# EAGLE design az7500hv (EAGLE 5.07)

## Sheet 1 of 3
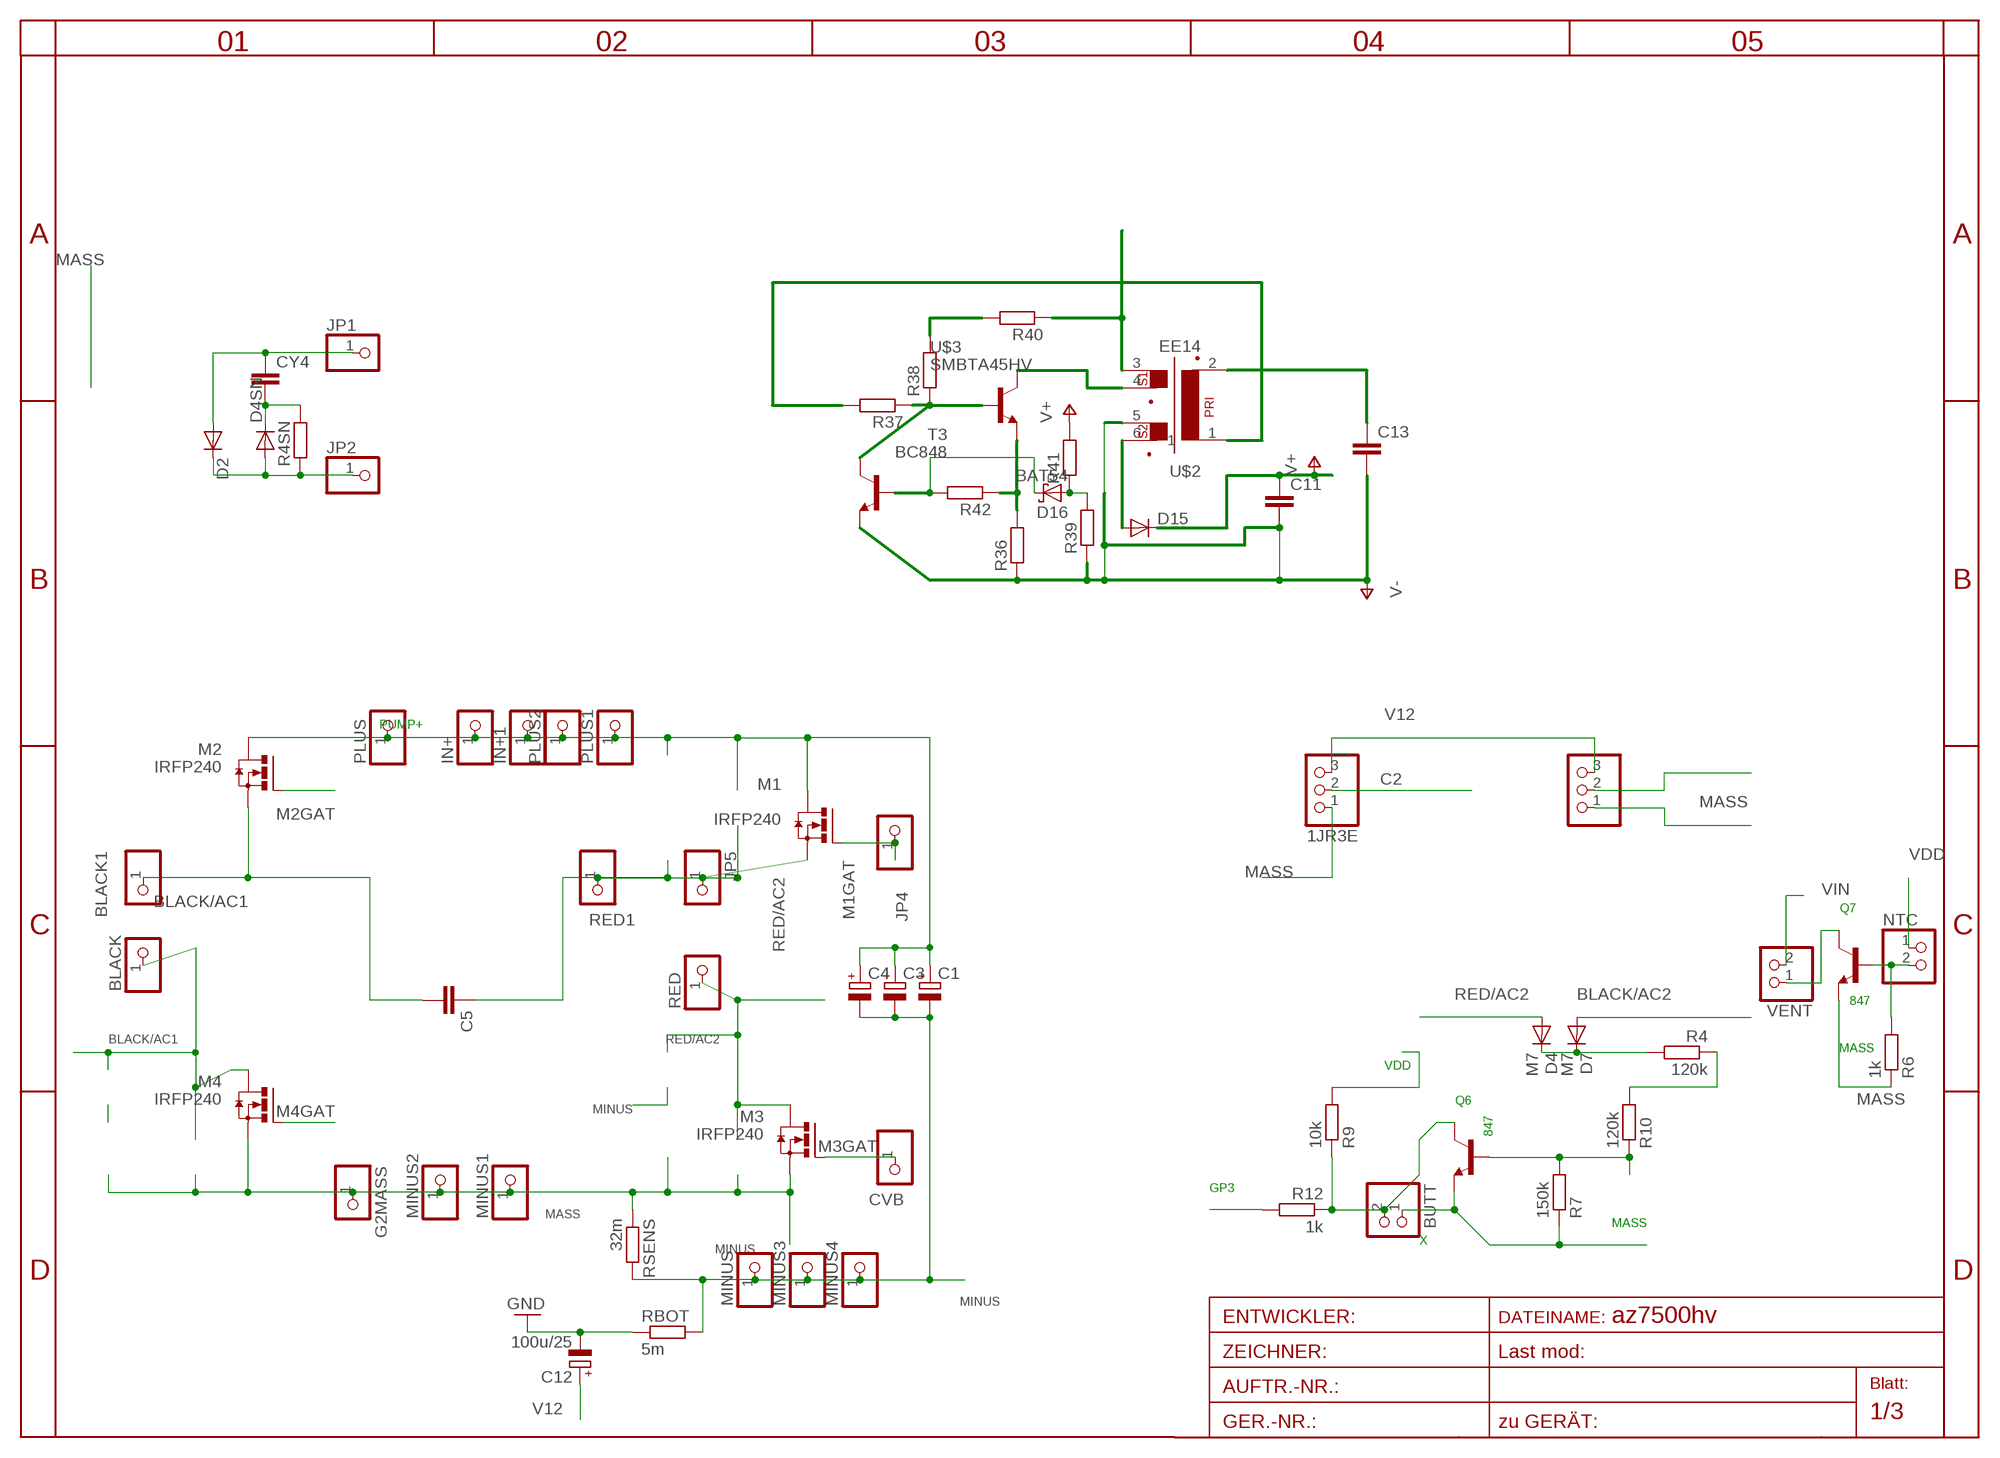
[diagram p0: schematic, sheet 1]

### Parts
1JR3E  PINHD-1X3  [1X03]
2JR4E3  PINHD-1X3  [1X03]
BLACK  PINHD-1X12MM3  [1X2MM3]
BLACK1  PINHD-1X12MM3  [1X2MM3]
BUTT  PINHD-1X2STR  [1X02]
C1  CPOL-EUE5-13  [E5-13]
C3  CPOL-EUE5-13  [E5-13]
C4  CPOL-EUE5-13  [E5-13]
C5  C-EU075-032X103  [C075-032X103]
C11  C-EUC1206  [C1206]
C12  100u/25  CPOL-EUE2.5-7  [E2,5-7]
C13  C-EUC0805  [C0805]
CVB  PINHD-1X11MM0  [1X1MM0]
CY4  CXXC10B5  [XC10B5]
D2  DIODE-SMC  [SMC]
D4  M7  1N4004DO41-10  [DO41-10]
D4SN  DIODE-P1-10  [P1-10]
D7  M7  1N4004DO41-10  [DO41-10]
D15  DIODE-SMA-DO214  [SMA-DO214AC]
D16  BAT54  [SOT23]
G2MASS  PINHD-1X11MM0  [1X1MM0]
IN+  PINHD-1X12MM3  [1X2MM3]
IN+1  PINHD-1X12MM3  [1X2MM3]
JP1  PINHD-1X11MM0  [1X1MM0]
JP2  PINHD-1X11MM0  [1X1MM0]
JP4  PINHD-1X11MM0  [1X1MM0]
JP5  PINHD-1X11MM0  [1X1MM0]
M1  IRFP240  [TO247BV]
M2  IRFP240  [TO247BV]
M3  IRFP240  [TO247BV]
M4  IRFP240  [TO247BV]
MINUS  PINHD-1X12MM3  [1X2MM3]
MINUS1  PINHD-1X12MM3  [1X2MM3]
MINUS2  PINHD-1X12MM3  [1X2MM3]
MINUS3  PINHD-1X12MM3  [1X2MM3]
MINUS4  PINHD-1X12MM3  [1X2MM3]
NTC  PINHD-1X2STR  [1X02]
PLUS  PINHD-1X12MM3  [1X2MM3]
PLUS1  PINHD-1X12MM3  [1X2MM3]
PLUS2  PINHD-1X12MM3  [1X2MM3]
Q6  847  BC847ALT1SMD  [SOT23]
Q7  847  BC847ALT1SMD  [SOT23]
R4  120k  R-EU_R1210  [R1210]
R4SN  R-EU_0207/10  [0207/10]
R6  1k  R-EU_R0805  [R0805]
R7  150k  R-EU_R0805  [R0805]
R9  10k  R-EU_R0805  [R0805]
R10  120k  R-EU_R1210  [R1210]
R12  1k  R-EU_R0805  [R0805]
R36  R-EU_R0805  [R0805]
R37  R-EU_R0805  [R0805]
R38  R-EU_R1206  [R1206]
R39  R-EU_R0805  [R0805]
R40  R-EU_R1206  [R1206]
R41  R-EU_R0805  [R0805]
R42  R-EU_R0805  [R0805]
RBOT  5m  R-EU_0204/7  [0204/7]
RED  PINHD-1X12MM3  [1X2MM3]
RED1  PINHD-1X12MM3  [1X2MM3]
RSENS  32m  R-EU_0204/7  [0204/7]
T3  BC848  [SOT23]
U$2  EE14  EE14EE14  [EE14]
U$3  SMBTA45HV  [SOT23HV]
VENT  PINHD-1X2STR  [1X02]

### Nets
A: D15.A U$2.6
B1C2: R37.1 R38.1 T3.C U$3.1(B)
BLACK/AC1: BLACK1.1 BLACK.1 C5.2 M2.S M4.D ; also sheet 2
BLACK/AC2: D7.A ; also sheet 2
C1: 2JR4E3.2 ; also sheet 2,3
C2: 1JR3E.2 ; also sheet 2,3
C3: U$2.4 U$3.3(C)
DRAIN: D2.C D4SN.A JP2.1 R4SN.1
EB: R36.2 R42.1 U$3.2(E)
GND: C12.- RBOT.1 ; also sheet 2
GP3: R12.2 ; also sheet 3
M1GAT: JP4.1 M1.G ; also sheet 2
M2GAT: M2.G ; also sheet 2
M3GAT: CVB.1 M3.G ; also sheet 2
M4GAT: M4.G ; also sheet 2
MASS: 1JR3E.1 2JR4E3.1 BUTT.1 G2MASS.1 M3.S M4.S MINUS1.1 MINUS2.1 Q6.2(E) Q7.2(E) R6.1 R7.1 RSENS.1 ; also sheet 2,3
MINUS: C1.- C3.- C4.- MINUS3.1 MINUS4.1 MINUS.1 RBOT.2 RSENS.2
N$1: D4.C D7.C R4.2
N$2: R37.2 U$2.1
N$5: Q6.1(B) R7.2 R10.1
N$7: R4.1 R10.2
N$9: NTC.2 Q7.1(B) R6.2
N$10: Q7.3(C) VENT.1
N$16: C13.1 U$2.2
N$37: R38.2 R40.2
N$38: D16.1(A) R39.2 R41.1
N$39: D16.3(C) R42.2 T3.B
OUT+: R40.1 U$2.3
PUMP+: C1.+ C3.+ C4.+ IN+1.1 IN+.1 M1.D M2.D PLUS1.1 PLUS2.1 PLUS.1 ; also sheet 3
RED/AC2: C5.1 D4.A JP5.1 M1.S M3.D RED1.1 RED.1 ; also sheet 2
SNUB2: CY4.2 D4SN.C R4SN.2
SOURCE: CY4.1 D2.A JP1.1
V12: 1JR3E.3 2JR4E3.3 C12.+
V+: C11.1 D15.K(C) R41.2
V-: C11.2 C13.2 R36.1 R39.1 T3.E U$2.5
VDD: NTC.1 R9.2 ; also sheet 3
VIN: VENT.2
X: BUTT.2 Q6.3(C) R9.1 R12.1

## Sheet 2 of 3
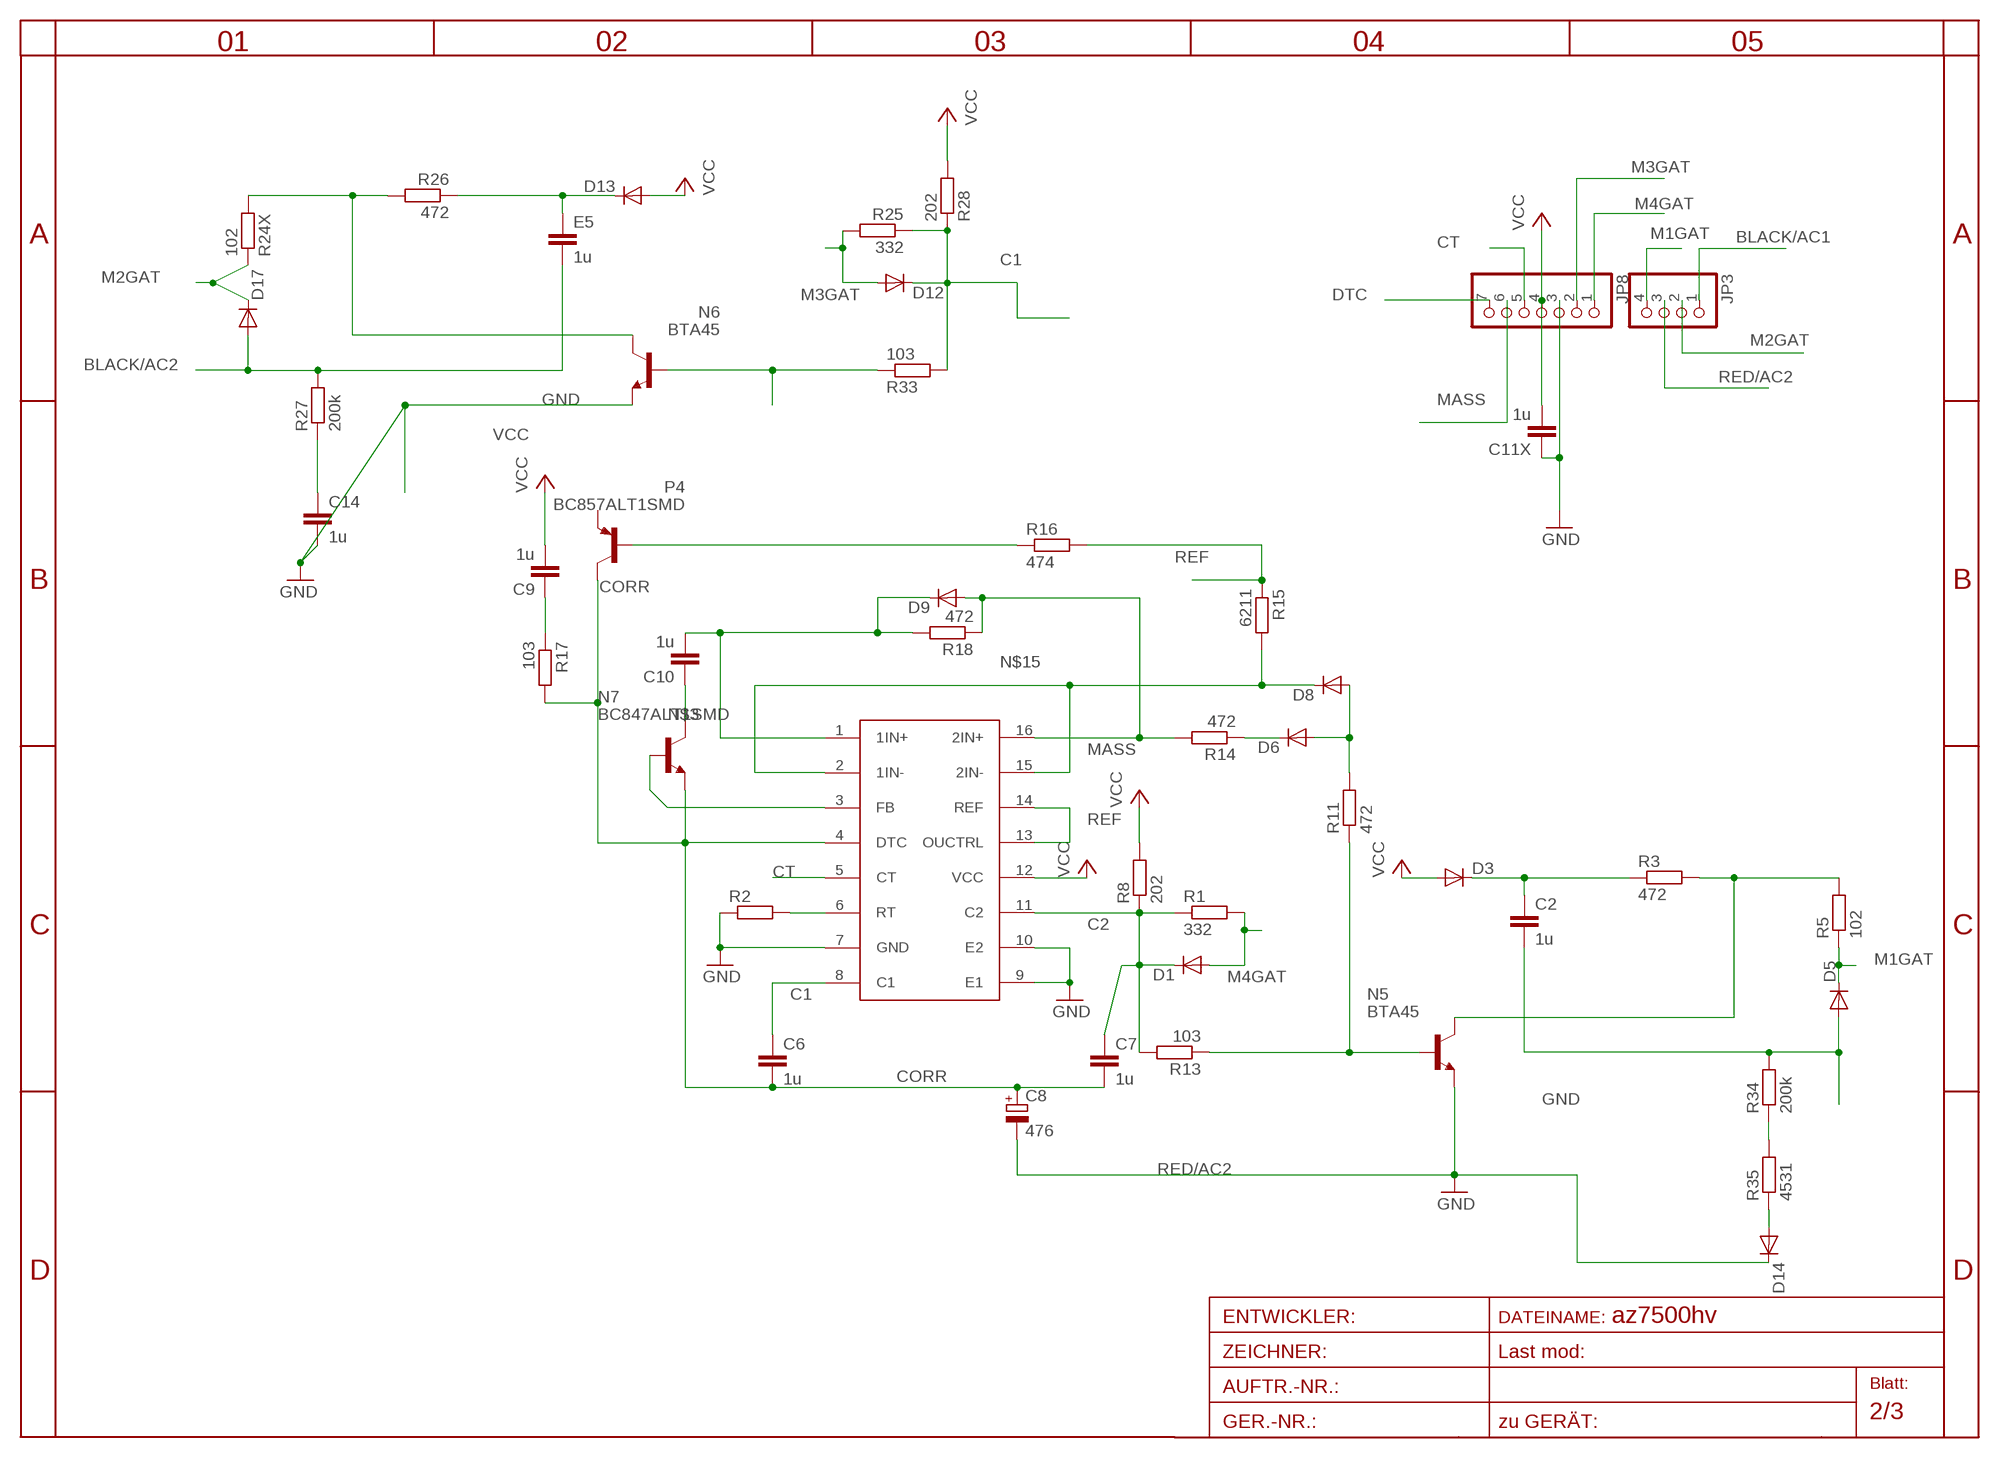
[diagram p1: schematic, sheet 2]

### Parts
C2  1u  C-EUC1206  [C1206]
C6  1u  C-EUC0805  [C0805]
C7  1u  C-EUC0805  [C0805]
C8  476  CPOL-EUD  [PANASONIC_D]
C9  1u  C-EUC0805  [C0805]
C10  1u  C-EUC0805  [C0805]
C11X  1u  C-EUC1206  [C1206]
C14  1u  C-EUC1206  [C1206]
D1  DIODE-MINIMELF  [MINIMELF]
D3  DIODE-SMA-DO214  [SMA-DO214AC]
D5  DIODE-MINIMELF  [MINIMELF]
D6  DIODE-MINIMELF  [MINIMELF]
D8  DIODE-MINIMELF  [MINIMELF]
D9  DIODE-MINIMELF  [MINIMELF]
D12  DIODE-MINIMELF  [MINIMELF]
D13  DIODE-SMA-DO214  [SMA-DO214AC]
D14  DIODE-MINIMELF  [MINIMELF]
D17  DIODE-MINIMELF  [MINIMELF]
E5  1u  C-EUC1206  [C1206]
JP3  PINHD-1X4  [1X04]
JP8  PINHD-1X7  [1X07]
N5  BTA45  SMBTA45HV  [SOT23HV]
N6  BTA45  SMBTA45HV  [SOT23HV]
N7  BC847ALT1SMD  [SOT23]
P4  BC857ALT1SMD  [SOT23-BEC]
R1  332  R-EU_R0805  [R0805]
R2  R-EU_R0805  [R0805]
R3  472  R-EU_R0805  [R0805]
R5  102  R-EU_R1206  [R1206]
R8  202  R-EU_R0805  [R0805]
R11  472  R-EU_R0805  [R0805]
R13  103  R-EU_0207/15  [0207/15]
R14  472  R-EU_R0805  [R0805]
R15  6211  R-EU_R1206  [R1206]
R16  474  R-EU_R1206  [R1206]
R17  103  R-EU_R1206  [R1206]
R18  472  R-EU_R0805  [R0805]
R24X  102  R-EU_R1206  [R1206]
R25  332  R-EU_R0805  [R0805]
R26  472  R-EU_R0805  [R0805]
R27  200k  R-EU_R0805  [R0805]
R28  202  R-EU_R0805  [R0805]
R33  103  R-EU_0207/15  [0207/15]
R34  200k  R-EU_R0805  [R0805]
R35  4531  R-EU_R0805  [R0805]
U$1  AZ7500SO16  [SO16]

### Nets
BLACK/AC1: JP3.1 ; also sheet 1
BLACK/AC2: D17.A E5.2 R27.2 ; also sheet 1
C1: C6.1 D12.C R25.1 R28.1 R33.2 U$1.8(C1) ; also sheet 1,3
C2: C7.1 D1.C R1.1 R8.1 R13.2 U$1.11(C2) ; also sheet 1,3
CORR: C6.2 C7.2 C8.+ N7.2(E) P4.C R17.2 U$1.4(DTC)
CT: JP8.5 U$1.5(CT)
DTC: JP8.7
GND: C8.- C11X.1 C14.2 D14.C JP8.3 N5.2(E) N6.2(E) R2.1 U$1.7(GND) U$1.9(E1) U$1.10(E2) ; also sheet 1
M1GAT: D5.C JP3.4 R5.1 ; also sheet 1
M2GAT: D17.C JP3.2 R24X.1 ; also sheet 1
M3GAT: D12.A JP8.2 R25.2 ; also sheet 1
M4GAT: D1.A JP8.1 R1.2 ; also sheet 1
MASS: D9.A JP8.6 R14.2 R18.1 U$1.16(2IN+) ; also sheet 1,3
N$3: C10.2 D9.C R18.2 U$1.1(1IN+)
N$4: C2.1 D3.K(C) R3.1
N$6: D6.A D8.A R11.2
N$8: N5.3(C) R3.2 R5.2
N$11: D6.C R14.1
N$13: D13.K(C) E5.1 R26.1
N$14: C14.1 R27.1
N$15: D8.C R15.2 U$1.2(1IN-) U$1.15(2IN-)
N$17: N5.1(B) R11.1 R13.1
N$18: C9.1 R17.1
N$19: N6.3(C) R24X.2 R26.2
N$20: N7.1(B) U$1.3(FB)
N$21: P4.B R16.1
N$23: R2.2 U$1.6(RT)
N$25: C10.1 N7.3(C)
N$29: N6.1(B) R33.1
N$33: R34.1 R35.2
N$36: D14.A R35.1
RED/AC2: C2.2 D5.A JP3.3 R34.2 ; also sheet 1
REF: R15.1 R16.2 U$1.13(OUCTRL) U$1.14(REF)
VCC: C9.2 C11X.2 D3.A D13.A JP8.4 R8.2 R28.2 U$1.12(VCC)
Unconnected: P4.E

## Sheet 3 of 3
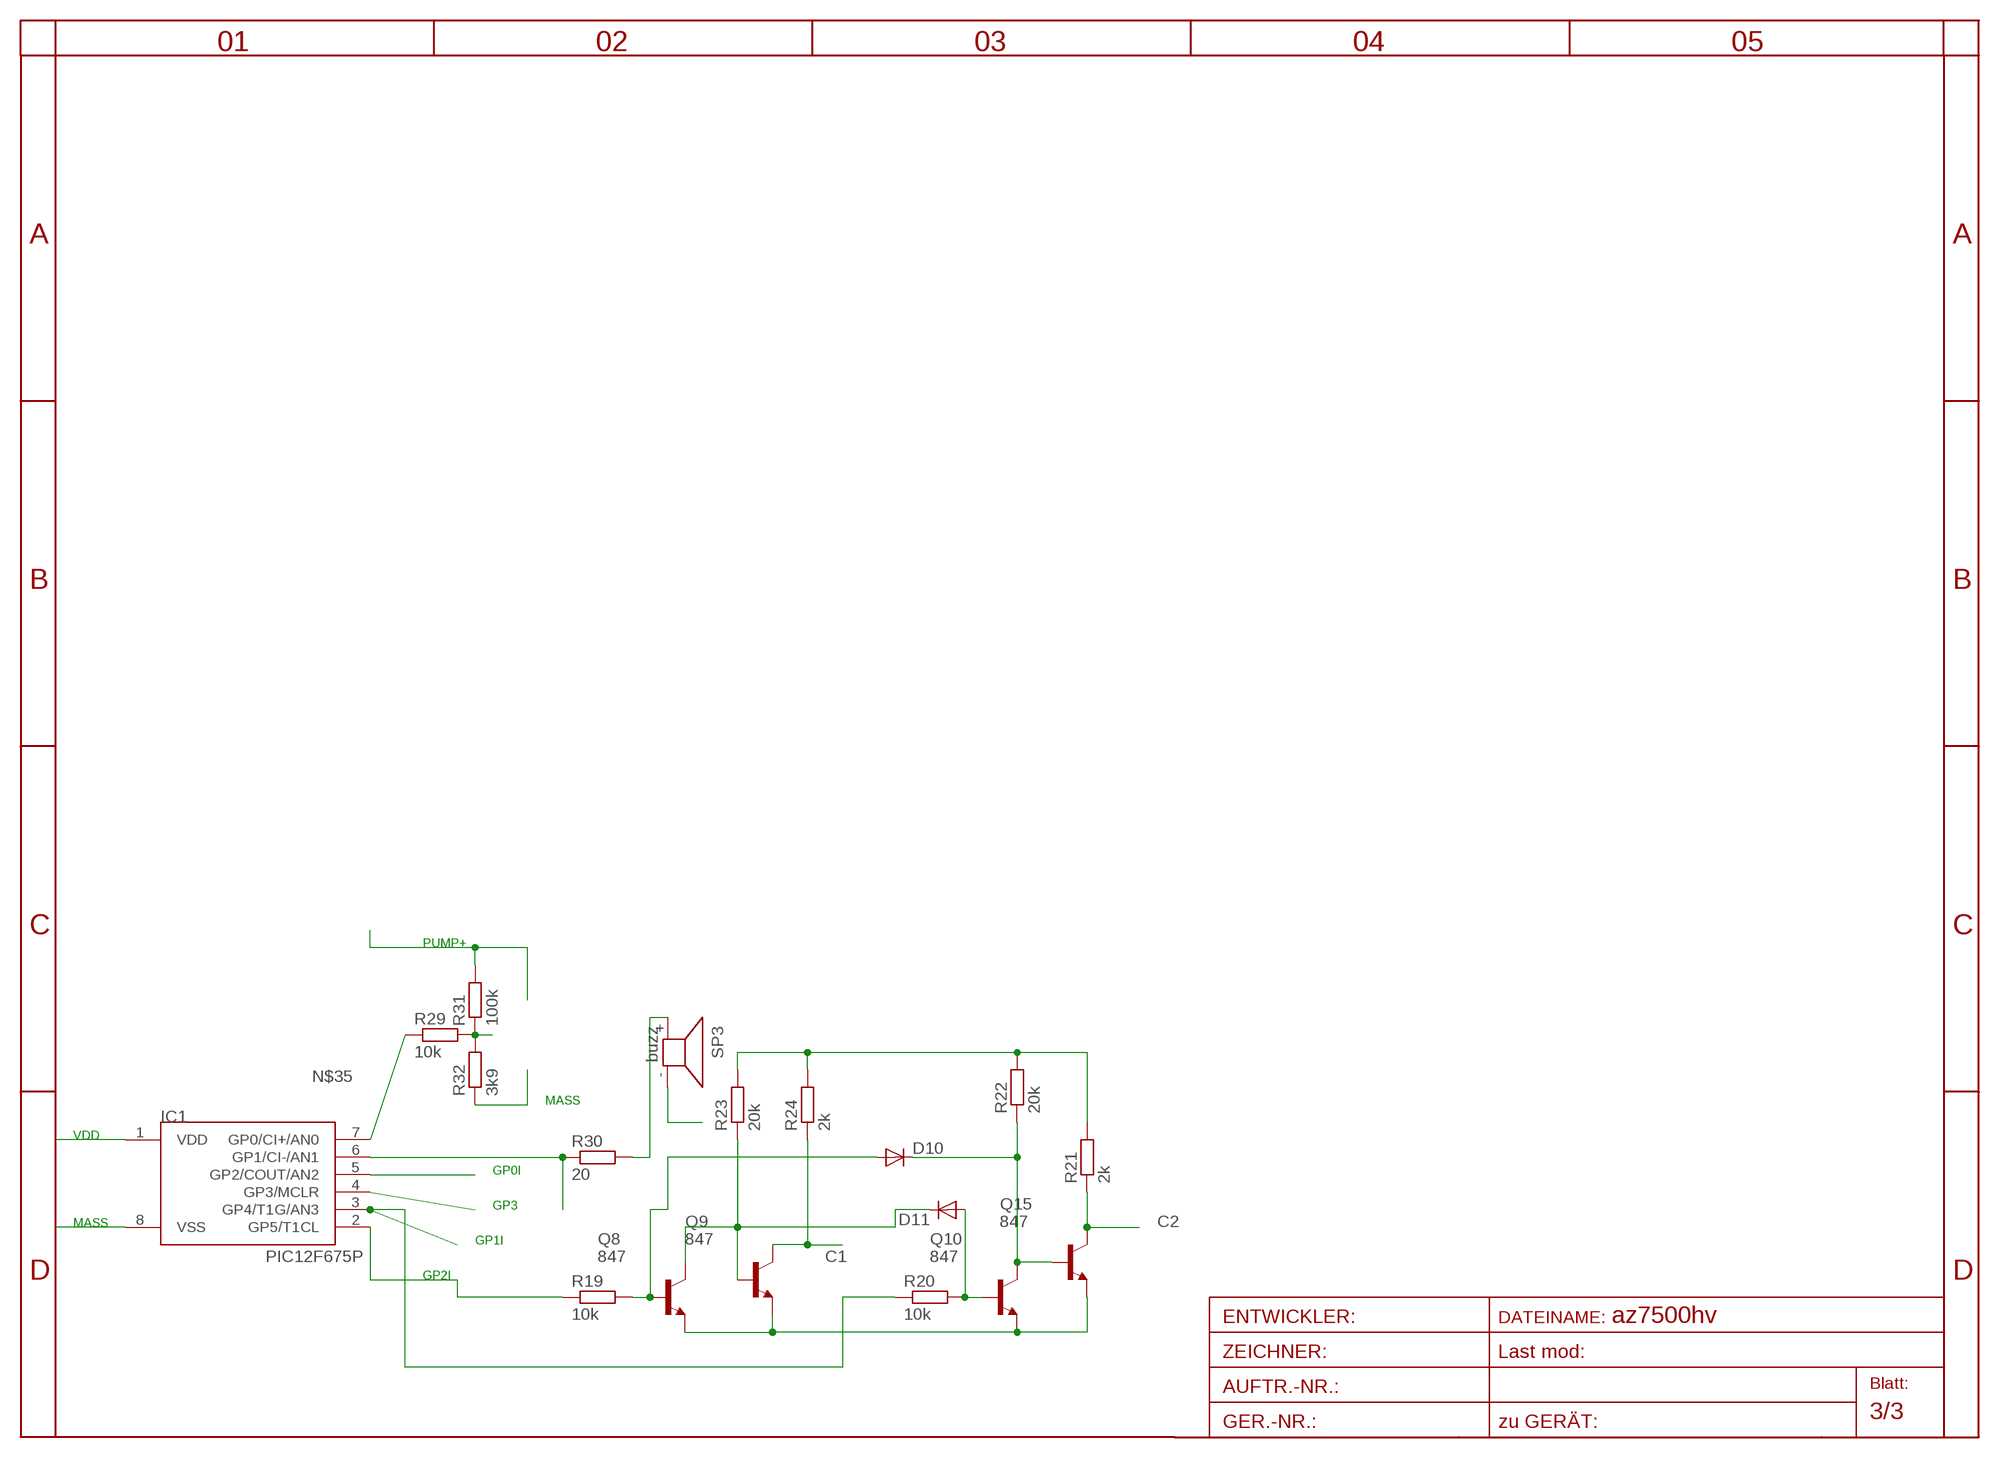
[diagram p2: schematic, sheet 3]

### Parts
D10  DIODE-MINIMELF  [MINIMELF]
D11  DIODE-MINIMELF  [MINIMELF]
IC1  PIC12F675P  [DIL8]
Q8  847  BC847ALT1SMD  [SOT23]
Q9  847  BC847ALT1SMD  [SOT23]
Q10  847  BC847ALT1SMD  [SOT23]
Q15  847  BC847ALT1SMD  [SOT23]
R19  10k  R-EU_R0805  [R0805]
R20  10k  R-EU_R0805  [R0805]
R21  2k  R-EU_R0805  [R0805]
R22  20k  R-EU_R0805  [R0805]
R23  20k  R-EU_R0805  [R0805]
R24  2k  R-EU_R0805  [R0805]
R29  10k  R-EU_R0805  [R0805]
R30  20  R-EU_R0805  [R0805]
R31  100k  R-EU_0207/25  [0207/25]
R32  3k9  R-EU_R0805  [R0805]
SP3  buzz  KSS12017MM  [KSS1202]

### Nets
C1: Q9.3(C) R24.1 ; also sheet 1,2
C2: Q15.3(C) R21.1 ; also sheet 1,2
GP0I: IC1.5(GP2/COUT/AN2)
GP1I: IC1.3(GP4/T1G/AN3) R20.1
GP2I: IC1.2(GP5/T1CL) R19.1
GP3: IC1.4(GP3/MCLR) ; also sheet 1
MASS: IC1.8(VSS) R32.1 SP3.- ; also sheet 1,2
N$22: D11.A Q10.1(B) R20.2
N$24: R30.2 SP3.+
N$26: D11.C Q8.3(C) Q9.1(B) R23.1
N$27: D10.C Q10.3(C) Q15.1(B) R22.1
N$28: D10.A Q8.1(B) R19.2
N$30: Q8.2(E) Q9.2(E) Q10.2(E) Q15.2(E)
N$31: IC1.6(GP1/CI-/AN1) R30.1
N$32: R21.2 R22.2 R23.2 R24.2
N$34: R29.2 R31.1 R32.2
N$35: IC1.7(GP0/CI+/AN0) R29.1
PUMP+: R31.2 ; also sheet 1
VDD: IC1.1(VDD) ; also sheet 1

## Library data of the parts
1JR3E 2JR4E3 = pinhead:PINHD-1X3: PIN HEADER
BLACK BLACK1 CVB G2MASS IN+ IN+1 JP1 JP2 JP4 JP5 MINUS MINUS1-MINUS4 PLUS PLUS1 PLUS2 RED RED1 = pinhead:PINHD-1X1: PIN HEADER
BUTT NTC VENT = pinhead:PINHD-1X2: PIN HEADER
C1 C3 C4 C8 C12 = rcl:CPOL-EU: POLARIZED CAPACITOR, European symbol
C2 C5-C7 C9-C11 C11X C13 C14 E5 = rcl:C-EU: CAPACITOR, European symbol
CY4 = rcl:CX: X CAPACITOR
D1-D3 D4SN D5 D6 D8-D15 D17 = diode:DIODE-: DIODE
D4 D7 = diode:1N4004: DIODE
D16 = diode:BAT54: Schottky Diodes
IC1 = microchip-5:PIC12F6*: uPC nW 1k Program Flash memory 2x Timer Comparator 10b A/D converter/ 4xIN
JP3 = pinhead:PINHD-1X4: PIN HEADER
JP8 = pinhead:PINHD-1X7: PIN HEADER
M1-M4 = transistor-power:IRFP240: HEXFET Power MosFet Source: http://www.irf.com/
N5 N6 U$3 = transistor-npn:SMBTA45
N7 Q6-Q10 Q15 = transistor-npn:BC847*: NPN Transistor
P4 = transistor-pnp:BC857*: PNP Transistror
R1-R4 R4SN R5-R18 R24X R25-R28 R33-R42 RBOT RSENS = rcl:R-EU_: RESISTOR, European symbol
R19-R24 R29-R32 = rcl-2:R-EU_: RESISTOR, European symbol
SP3 = buzzer:KSS1201: SPEAKER
T3 = transistor:BC848: NPN TRANSISTOR
U$1 = az7500:AZ7500
U$2 = trafo:EE14

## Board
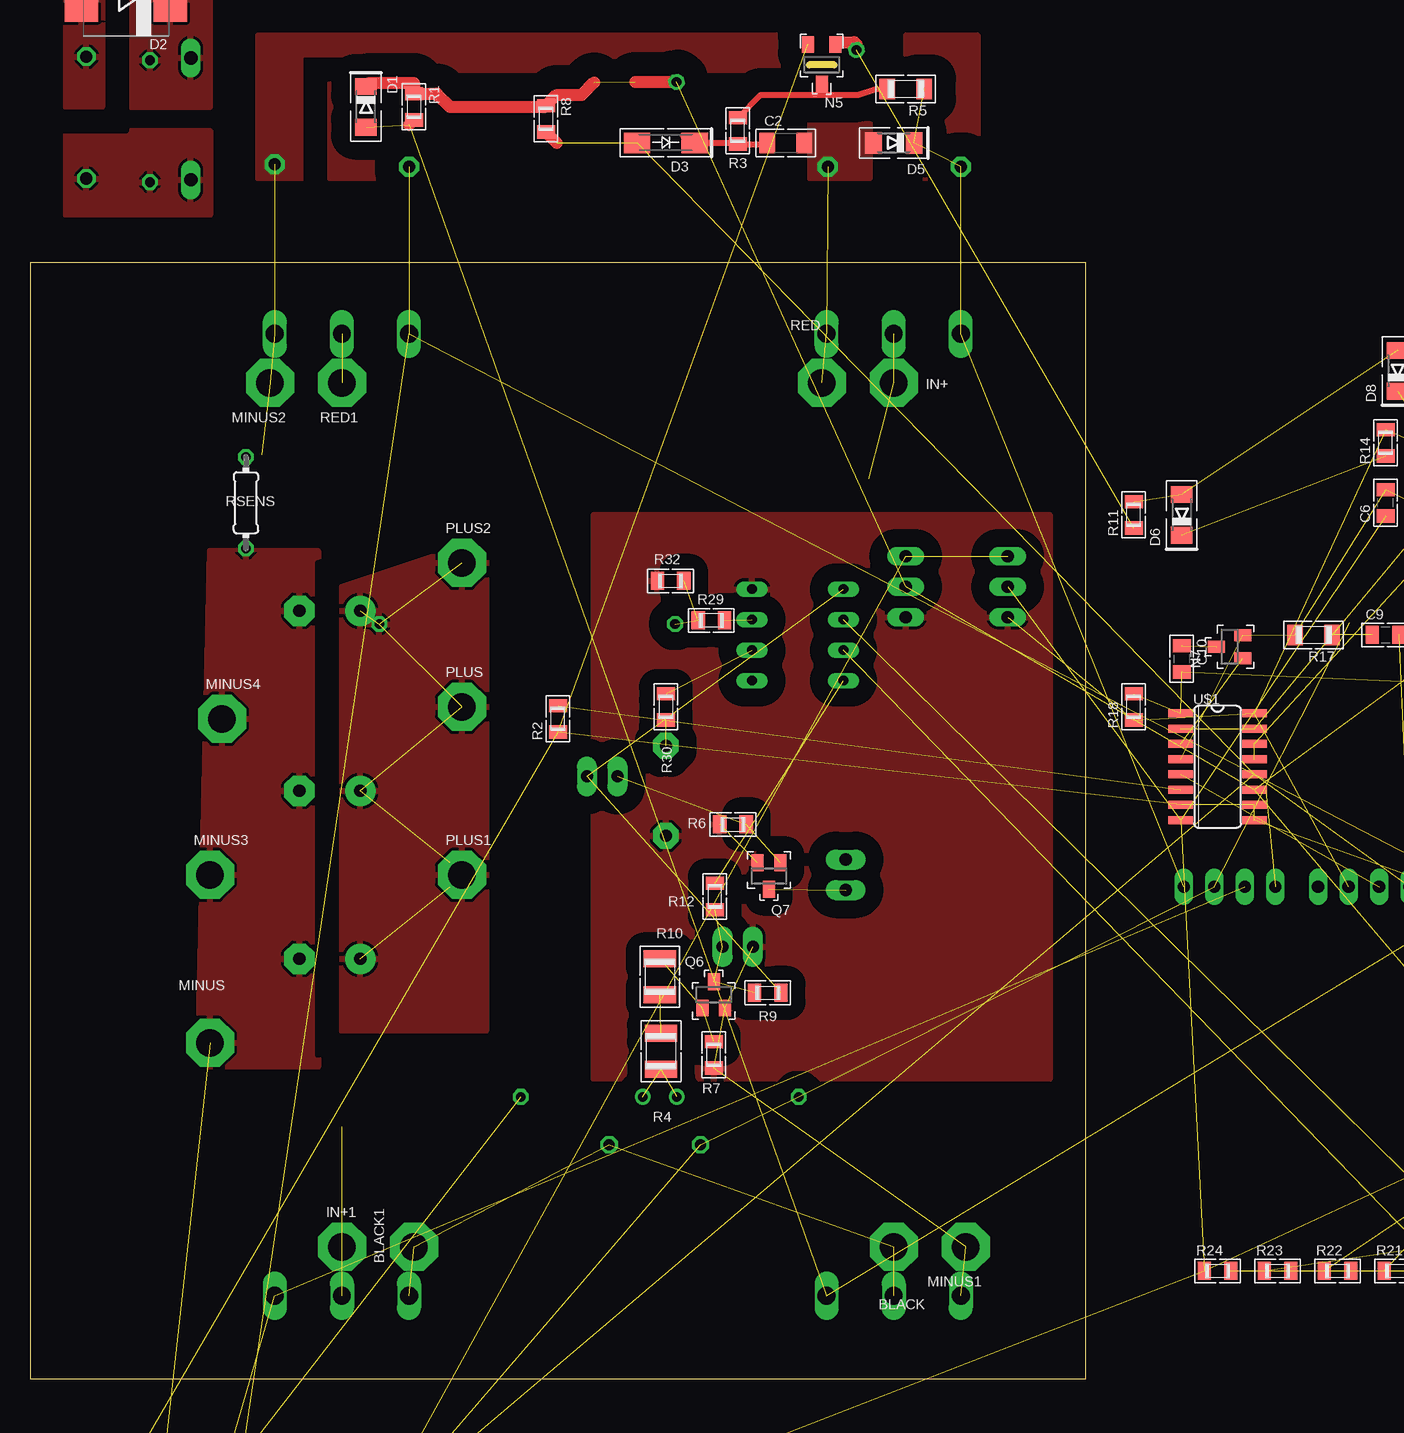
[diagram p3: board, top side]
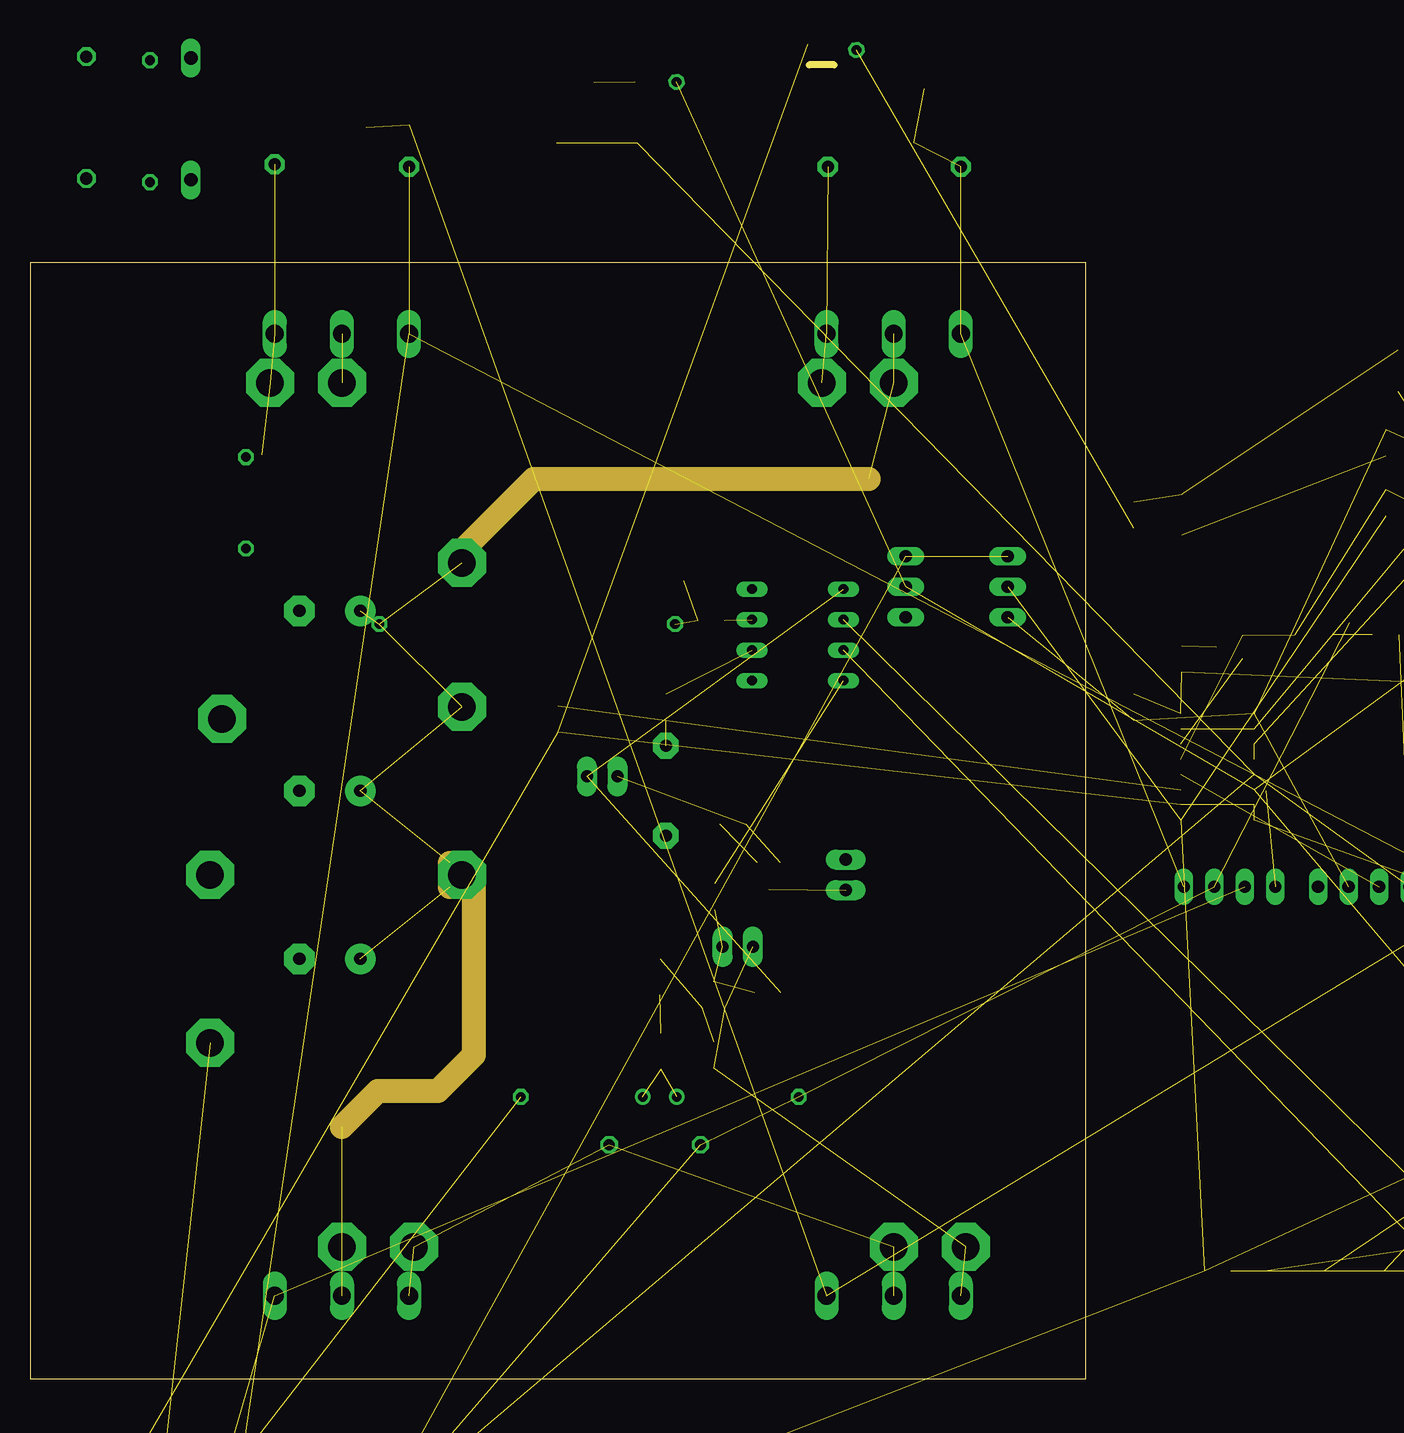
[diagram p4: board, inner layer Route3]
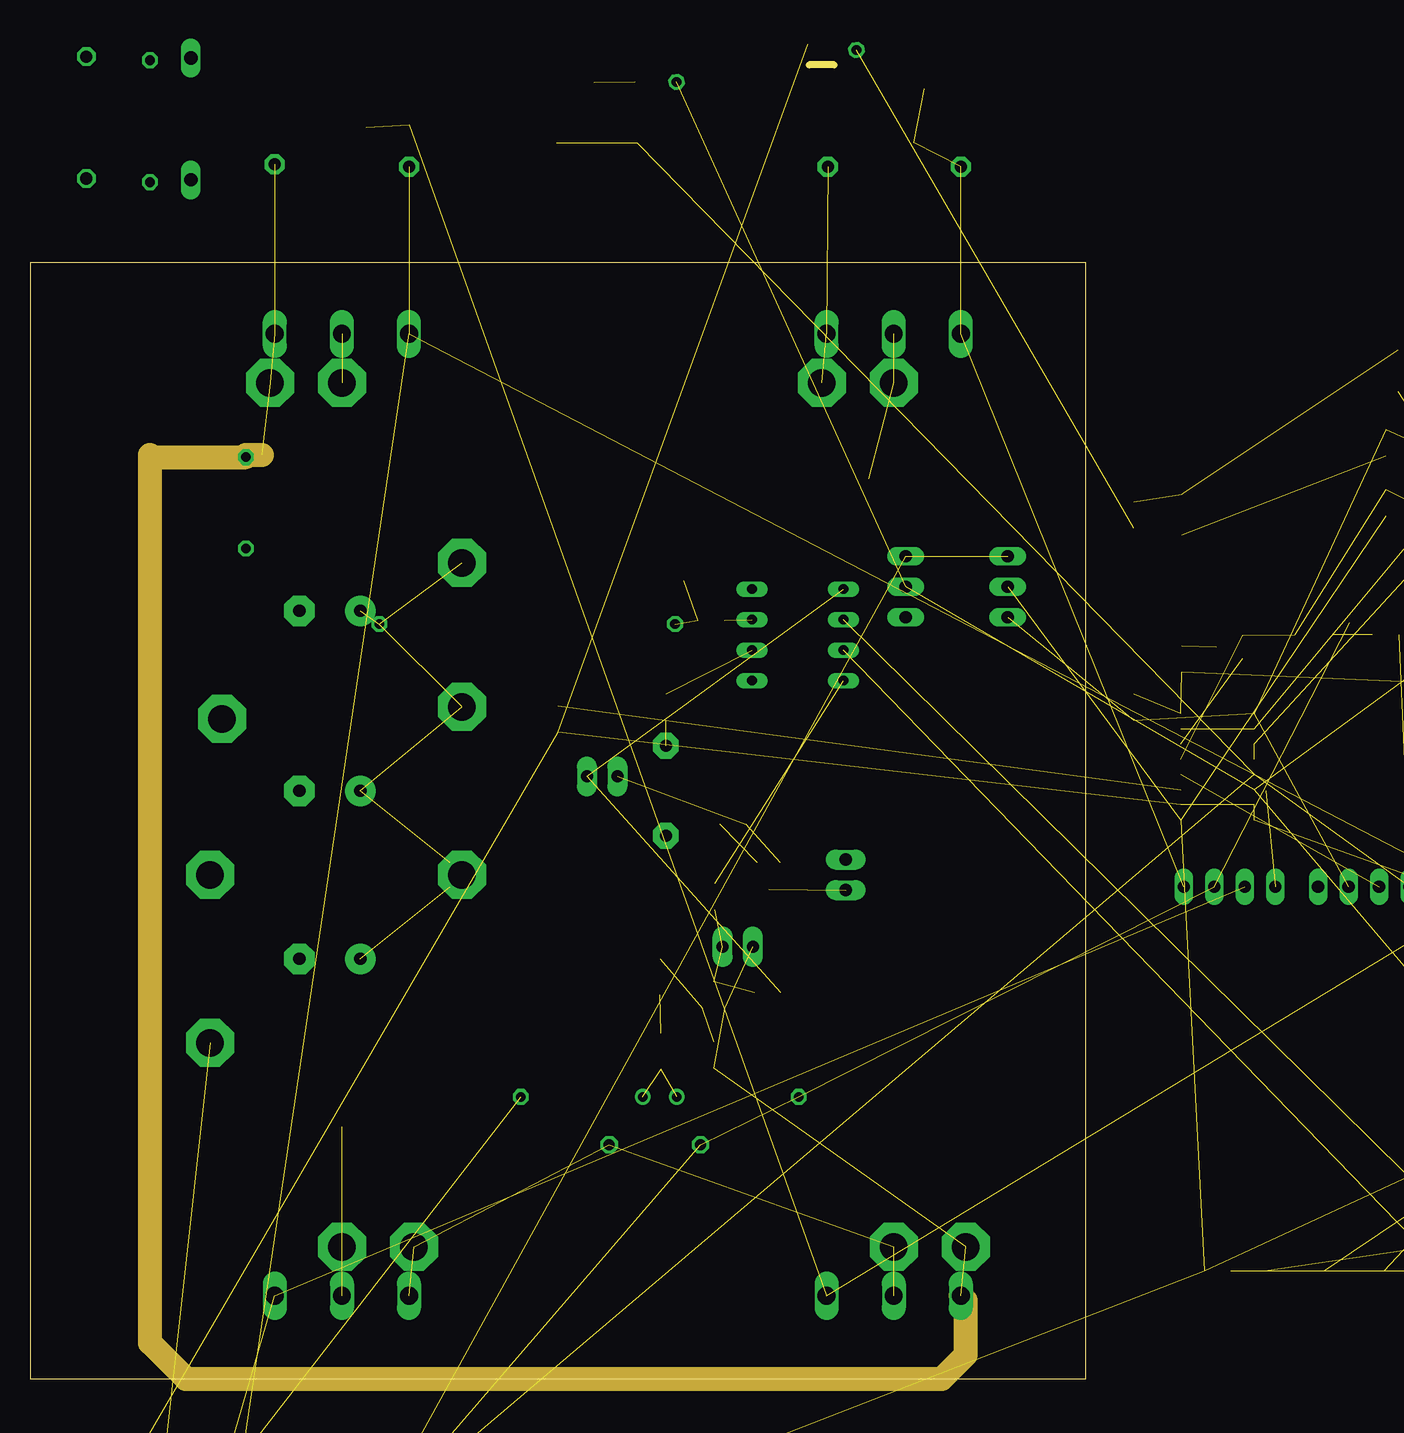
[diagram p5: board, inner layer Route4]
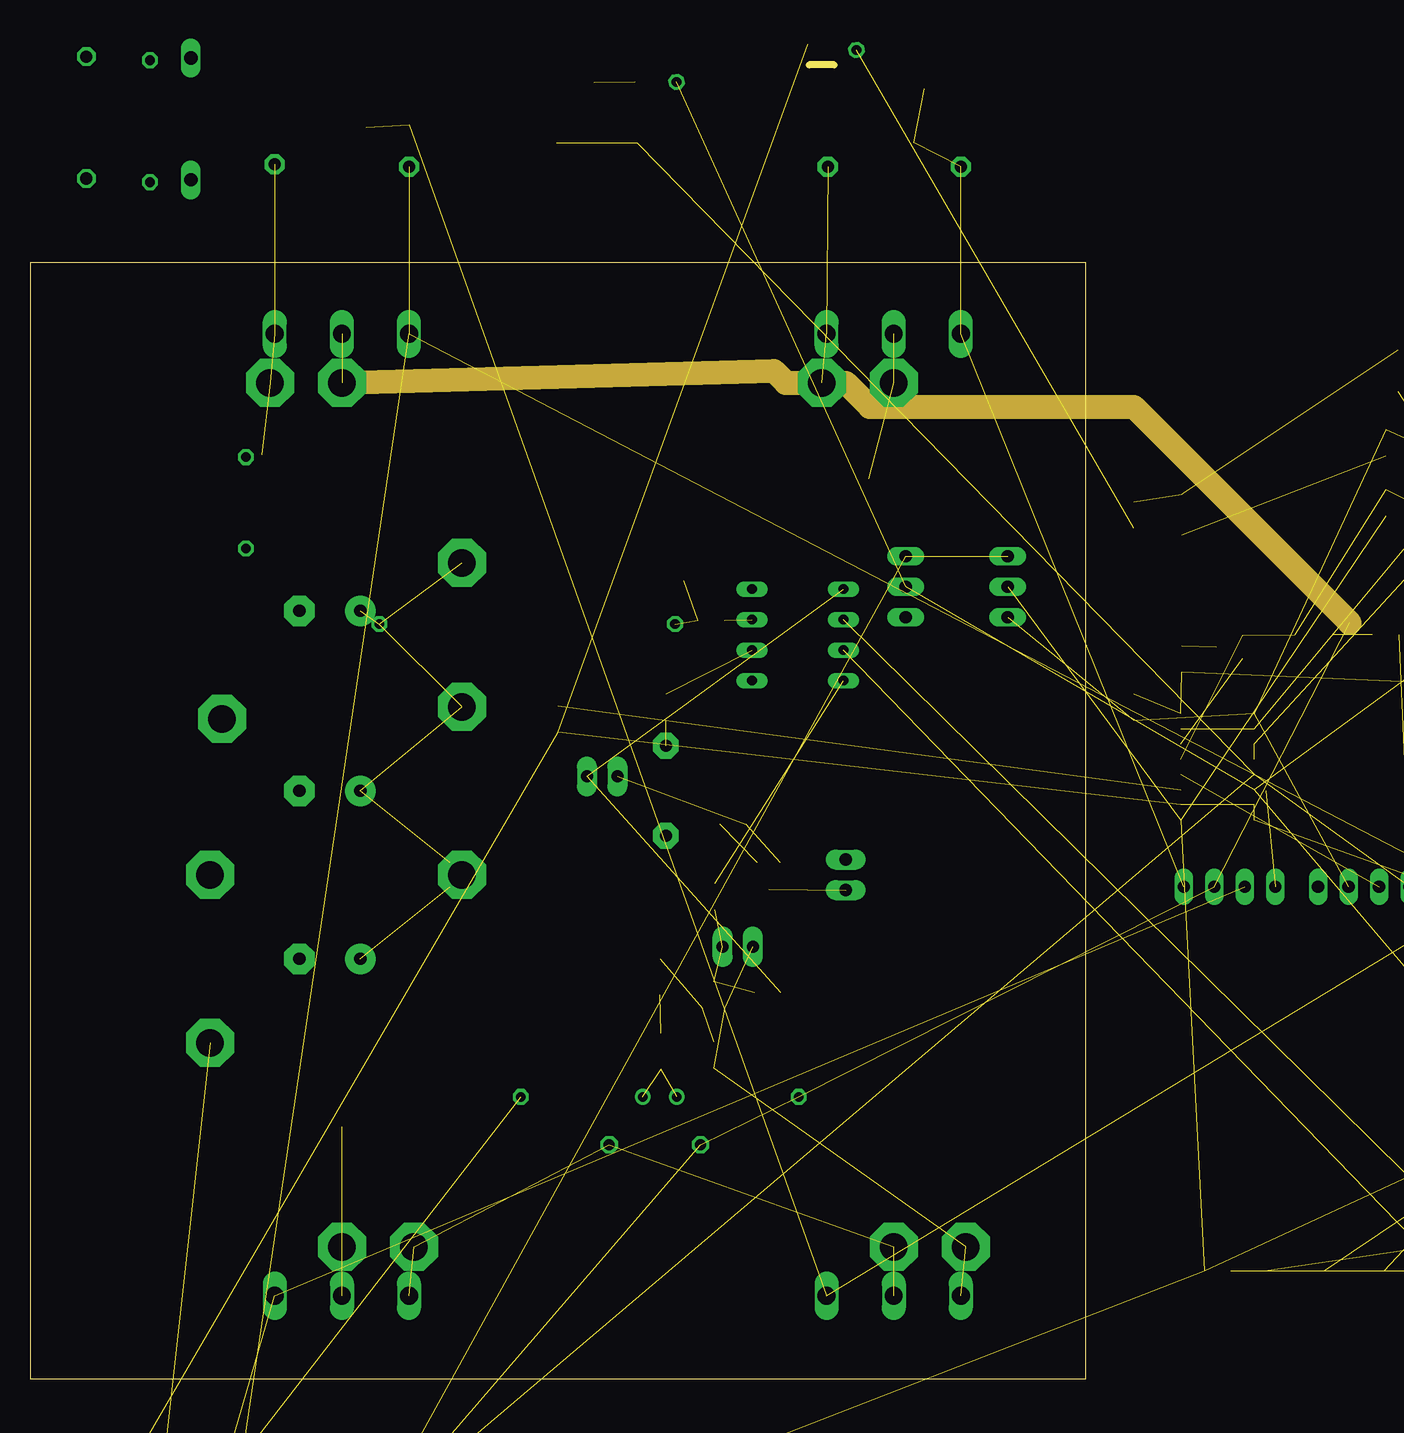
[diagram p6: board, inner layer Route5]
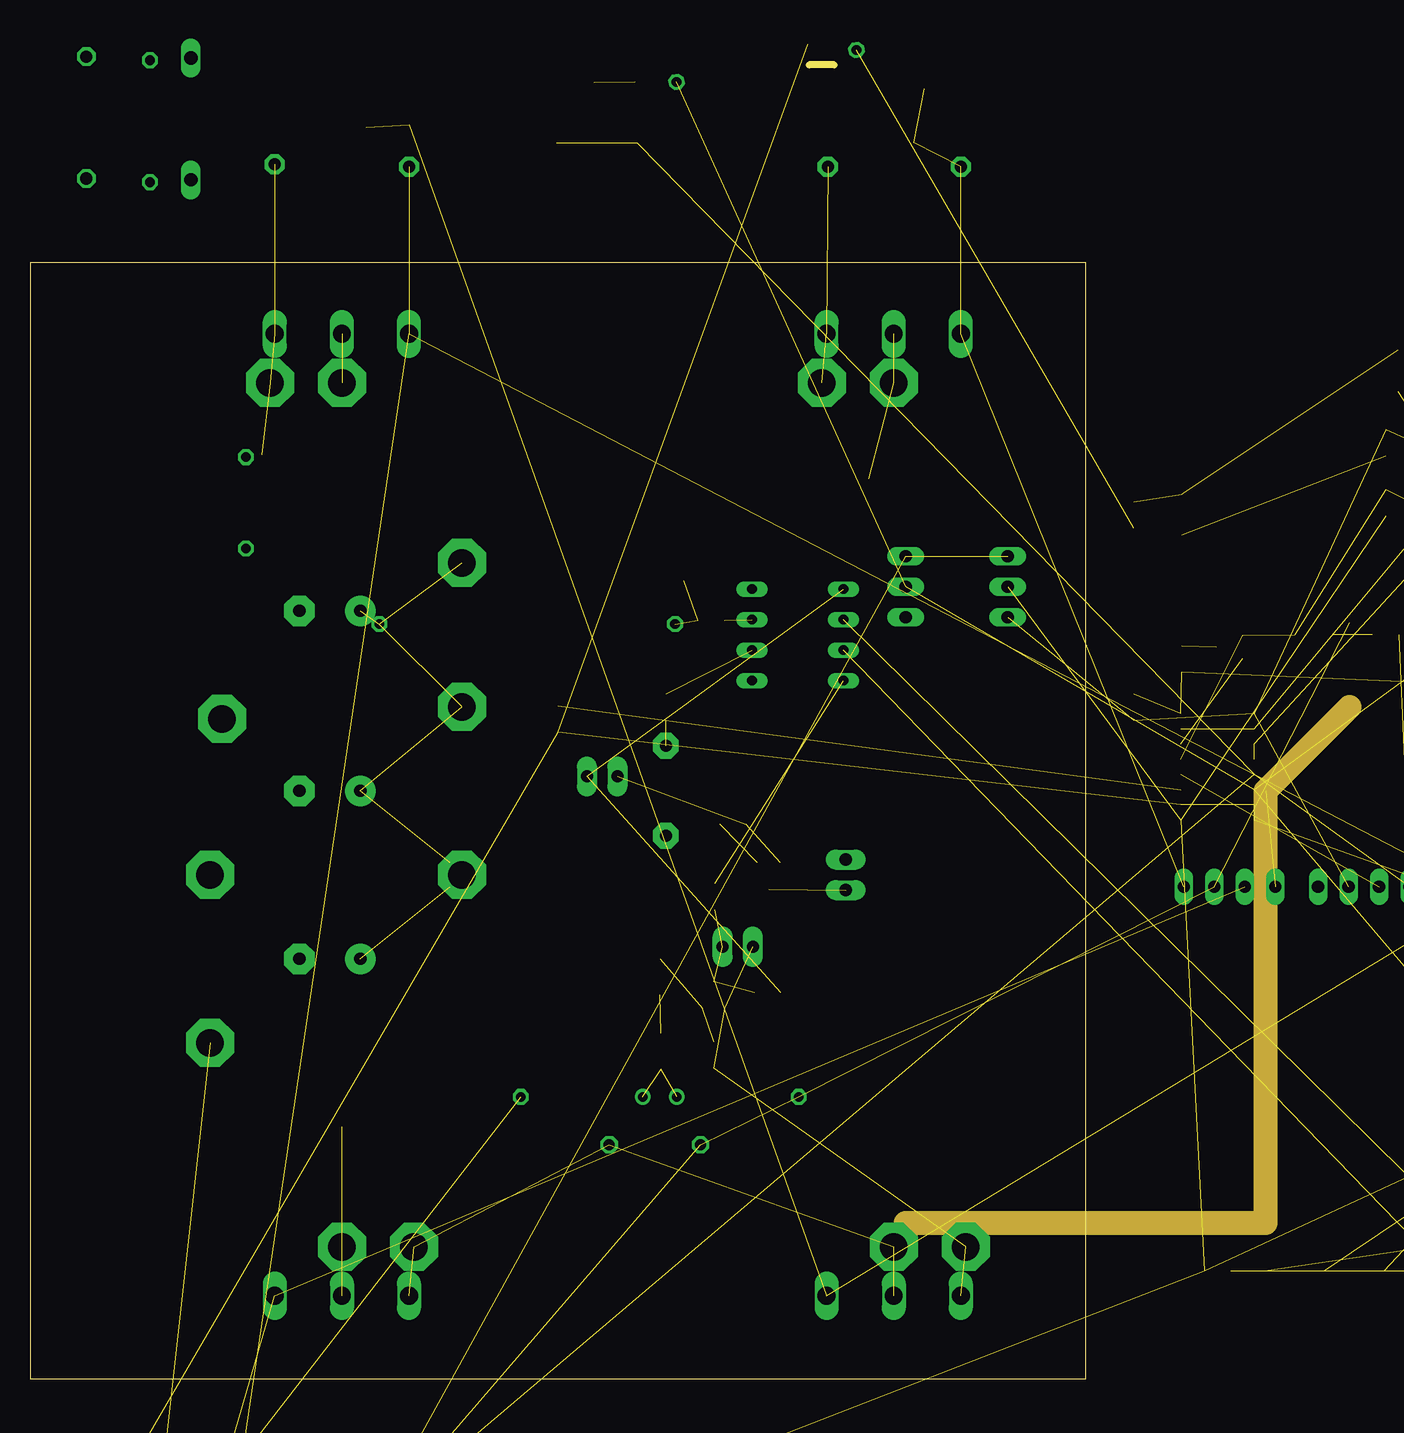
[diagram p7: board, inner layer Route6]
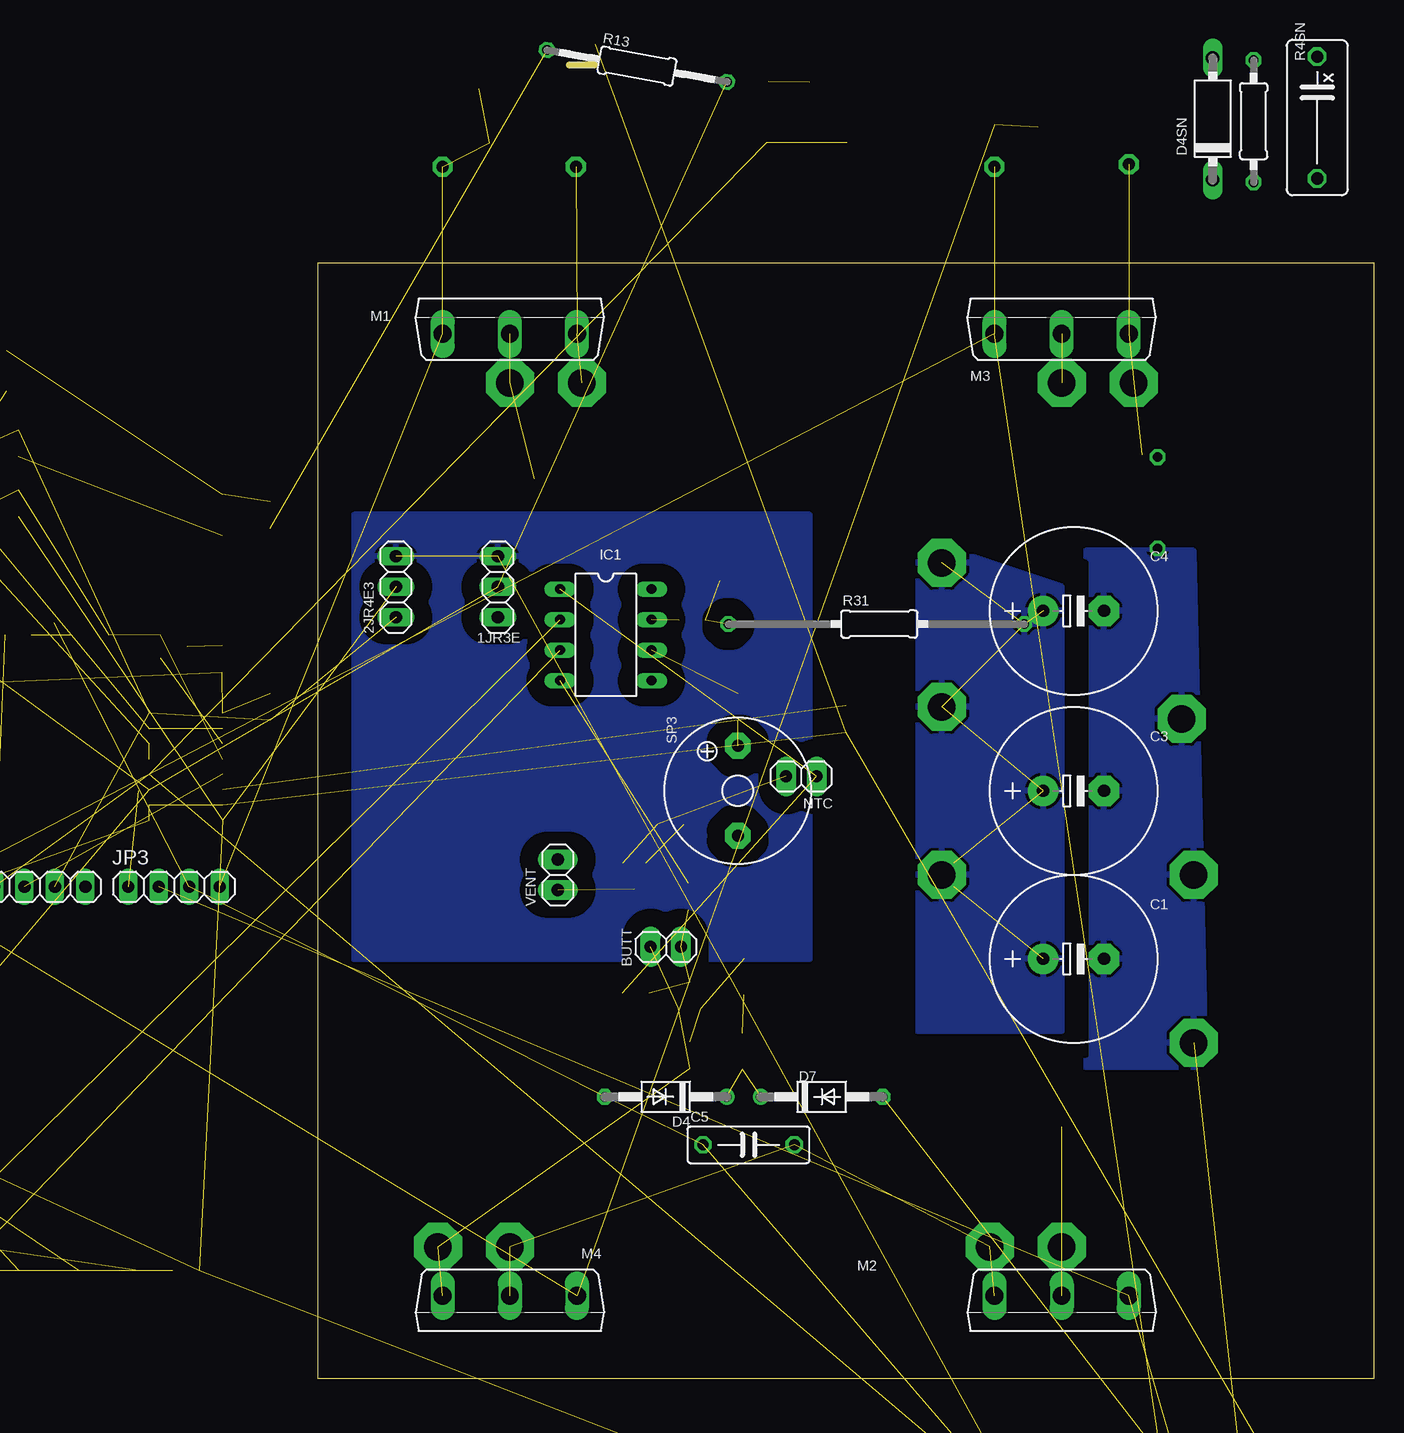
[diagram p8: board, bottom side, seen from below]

Size 88 x 93 mm. Coordinates in mm from the lower left corner, seen from the top.
Outline: 0,0 88,0 88,93 0,93 0,0
Copper layers (1*16): Top 0.035mm / dielectric 1.5mm / Bottom 0.035mm
Design rules "default *": minimum track width 10mil, minimum drill 20mil, track to track 8mil, track to pad 8mil, pad to pad 8mil, via to via 8mil, smd to smd 8mil, copper to edge 40mil, drill to drill 8mil, minimum pad ring 10mil, minimum via ring 8mil, stop-mask expansion 4mil, vias tented up to drill 0mil, thermal gap 10mil

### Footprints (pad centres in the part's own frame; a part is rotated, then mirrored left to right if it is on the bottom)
1X03 = drill 1.016 long: 1 -2.54,0; 2 0,0; 3 2.54,0
1X2MM3 = drill 2.3 pad 4 octagon: 1 0,0
1X02 = drill 1.016 pad 1.676 long: 1 -1.27,0; 2 1.27,0
E5-13 = drill 1.016 pad 2.54 round: + -2.54,0 | drill 1.016 pad 2.54 octagon: - 2.54,0
C1206 = smd 1.3 x 1.7: 1 -1.55,0; 2 1.55,0
C075-032X103 = drill 0.914 octagon: 1 -3.81,0; 2 3.81,0
C0805 = smd 1.1 x 1.5: 1 -1.1,0; 2 1.1,0
PANASONIC_D = smd 3 x 1.4: + 3,0; - -3,0
E2,5-7 = drill 0.813 pad 1.6 round: + -1.27,0 | drill 0.813 pad 1.6 octagon: - 1.27,0
1X1MM0 = drill 1 pad 1.676 octagon: 1 0,0
XC10B5 = drill 1.016 octagon: 1 -5.08,0; 2 5.08,0
MINIMELF = smd 1.4 x 1.8: A 1.7,0; C -1.7,0
SMC = smd 2.8 x 3.8: A 3.7,0; C -3.7,0
SMA-DO214AC = smd 2.2 x 1.7: A 2.4,0; K -2.4,0
DO41-10 = drill 0.8 octagon: A 5.08,0 | drill 0.8 round: C -5.08,0
P1-10 = drill 1.118 long: A 5.08,0; C -5.08,0
SOT23 = smd 1 x 1.4: 1 -0.95,-1.1; 2 0.95,-1.1; 3 0,1.1
DIL8 = drill 0.8 long: 1 -3.81,-3.81; 2 -1.27,-3.81; 3 1.27,-3.81; 4 3.81,-3.81; 5 3.81,3.81; 6 1.27,3.81; 7 -1.27,3.81; 8 -3.81,3.81
1X04 = drill 1.016 long: 1 -3.81,0; 2 -1.27,0; 3 1.27,0; 4 3.81,0
1X07 = drill 1.016 long: 1 -7.62,0; 2 -5.08,0; 3 -2.54,0; 4 0,0; 5 2.54,0; 6 5.08,0; 7 7.62,0
TO247BV = drill 1.499 long: D 0,-2.921; G -5.588,-2.921; S 5.588,-2.921
SOT23HV = smd 1 x 1.4: 1 -1.15,-1.7; 2 1.15,-1.7; 3 0,1.6
SOT23-BEC = smd 1 x 1.4: B -0.95,-1.1; C 0,1.1; E 0.95,-1.1
R0805 = smd 1.1 x 1.5: 1 -1.1,0; 2 1.1,0
R1210 = smd 1.4 x 2.7: 1 -1.5,0; 2 1.5,0
0207/10 = drill 0.813 octagon: 1 -5.08,0; 2 5.08,0
R1206 = smd 1.3 x 1.7: 1 -1.55,0; 2 1.55,0
0207/15 = drill 0.813 octagon: 1 -7.62,0; 2 7.62,0
0207/25 = drill 0.813 octagon: 1 -12.58,0; 2 12.08,0
0204/7 = drill 0.813 octagon: 1 -3.81,0; 2 3.81,0
KSS1202 = drill 1 pad 2.159 octagon: + 3.75,0; - -3.75,0
SOT23' = smd 1 x 1.4: B -0.95,-1.1; C 0,1.1; E 0.95,-1.1
SO16 = smd 2.032 x 0.66: 1 -3.073,4.445; 2 -3.073,3.175; 3 -3.073,1.905; 4 -3.073,0.635; 5 -3.073,-0.635; 6 -3.073,-1.905; 7 -3.073,-3.175; 8 -3.073,-4.445; 9 3.073,-4.445; 10 3.073,-3.175; 11 3.073,-1.905; 12 3.073,-0.635; 13 3.073,0.635; 14 3.073,1.905; 15 3.073,3.175; 16 3.073,4.445
EE14 = drill 0.6 pad 1.2 long: 1 4.25,-5; 2 4.25,5; 3 -4.25,5; 4 -4.25,2.5; 5 -4.25,-2.5; 6 -4.25,-5

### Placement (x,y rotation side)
1JR3E  73,66 90 bottom
2JR4E3  81.5,66 90 bottom
BLACK  72,11 180 top
BLACK1  32,11 90 top
BUTT  59,36 0 bottom
C1  25,35 0 bottom
C2  63,103 0 top  (outside the outline)
C3  25,49 0 bottom
C4  25,64 0 bottom
C5  52.1,19.5 0 bottom
C6  not placed on the board
C7  not placed on the board
C8  not placed on the board
C9  not placed on the board
C10  not placed on the board
C11  not placed on the board
C11X  not placed on the board
C12  not placed on the board
C13  not placed on the board
C14  not placed on the board
CVB  not placed on the board
CY4  not placed on the board
D1  28,106 270 top  (outside the outline)
D2  not placed on the board
D3  53,103 180 top  (outside the outline)
D4  59,23.5 180 bottom
D4SN  not placed on the board
D5  not placed on the board
D6  not placed on the board
D7  46,23.5 0 bottom
D8  not placed on the board
D9  not placed on the board
D10  not placed on the board
D11  not placed on the board
D12  not placed on the board
D13  not placed on the board
D14  not placed on the board
D15  not placed on the board
D16  not placed on the board
D17  not placed on the board
E5  not placed on the board
G2MASS  not placed on the board
IC1  64,62 270 bottom
IN+  72,83 0 top
IN+1  26,11 0 top
JP1  not placed on the board
JP2  not placed on the board
JP3  not placed on the board
JP4  not placed on the board
JP5  66.5,101 180 top  (outside the outline)
JP8  not placed on the board
M1  72,90 0 bottom
M2  26,4 180 bottom
M3  26,90 0 bottom
M4  72,4 180 bottom
MINUS  15,28 0 top
MINUS1  78,11 180 top
MINUS2  20,83 180 top
MINUS3  15,42 0 top
MINUS4  16,55 0 top
N5  66,109.5 180 top  (outside the outline)
N6  not placed on the board
N7  not placed on the board
NTC  47.7,50.2 180 bottom
P4  not placed on the board
PLUS  36,56 0 top
PLUS1  36,42 0 top
PLUS2  36,68 0 top
Q6  57,32 0 top
Q7  61.6,41.9 180 top
Q8  not placed on the board
Q9  not placed on the board
Q10  not placed on the board
Q15  not placed on the board
R1  32,106 270 top  (outside the outline)
R2  44,55 90 top
R3  59,104 90 top  (outside the outline)
R4  52.6,27.3 270 top
R4SN  not placed on the board
R5  73,107.5 180 top  (outside the outline)
R6  58.6,46.2 0 top
R7  57,27 90 top
R8  43,105 270 top  (outside the outline)
R9  61.5,32.17 0 top
R10  52.5,33.5 270 top
R11  not placed on the board
R12  57.1,40.2 90 top
R13  61.4,109.4 350 bottom  (outside the outline)
R14  not placed on the board
R15  not placed on the board
R16  not placed on the board
R17  not placed on the board
R18  not placed on the board
R19  not placed on the board
R20  not placed on the board
R21  not placed on the board
R22  not placed on the board
R23  not placed on the board
R24  not placed on the board
R24X  not placed on the board
R25  not placed on the board
R26  not placed on the board
R27  not placed on the board
R28  not placed on the board
R29  56.8,63.2 180 top
R30  53,56 270 top
R31  41.2,62.9 0 bottom
R32  53.4,66.5 0 top
R33  not placed on the board
R34  not placed on the board
R35  not placed on the board
R36  not placed on the board
R37  not placed on the board
R38  not placed on the board
R39  not placed on the board
R40  not placed on the board
R41  not placed on the board
R42  not placed on the board
RBOT  not placed on the board
RED  66,83 0 top
RED1  26,83 180 top
RSENS  18,73 270 top
SP3  53,49 90 bottom
T3  BC848  [SOT23']  not placed on the board
U$1  not placed on the board
U$2  not placed on the board
U$3  not placed on the board
VENT  68,42 90 bottom

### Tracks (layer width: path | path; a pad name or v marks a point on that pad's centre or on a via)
A  (1 unrouted)
B1C2  (3 unrouted)
BLACK/AC1  (5 unrouted)
  Route6 2: BLACK.1 73,12 73,13 103,13 103,49 110,56
BLACK/AC2  (3 unrouted)
C1  (8 unrouted)
C2  (6 unrouted)
  Top 1: 50.45,108.08 R13.2 | 47.03,108.03 46,107 43.9,107 R8.1 42.9,106 35,106 33.9,107.1 R1.1 32,108 28.3,108 D1.C
C3  (1 unrouted)
CORR  (6 unrouted)
CT  (1 unrouted)
DRAIN
  pour Top (isolate 2, rank 2): 8,120 8,106 15,106 15,120
EB  (2 unrouted)
GAT1
  pour Top (isolate 2): 25,100 25,108 33,108 33,100
GAT3
  pour Top (isolate 2, rank 2): 73,112 79,112 79,100 73,100
GND  (12 unrouted)
GP1I  (1 unrouted)
GP2I  (1 unrouted)
GP3  (1 unrouted)
M1GAT  (4 unrouted)
M2GAT  (3 unrouted)
M3GAT  (4 unrouted)
M4GAT  (3 unrouted)
  Top 1: R1.2 31.6,104.5
MASS  (13 unrouted)
  Route4 2: 19.33,77 18,77 RSENS.1 10.19,76.81 10,77 10,3 13,0 76,0 78,2 78,6.51 M4.S
  pour Top (isolate 1.5): 47,72 85,72 85,25 47,25
  pour Top (isolate 2, rank 2, no thermals): 19,112 65,112 65,109 23,109 23,100 19,100
MINUS  (1 unrouted)
  pour Top (isolate 2, rank 2): 15,69 24,69 24,26 14,26
  pour Bottom (isolate 2, rank 2): 15,69 24,69 24,26 14,26
N$1  (2 unrouted)
N$2  (1 unrouted)
N$3  (3 unrouted)
N$4
  Top 0.5: C2.1 61.8,102.9 R3.1 58.9,103 55,103 54.4,103.6 D3.K
N$5  (2 unrouted)
N$6  (2 unrouted)
N$7  (1 unrouted)
N$8
  Top 0.5: R5.2 70.45,107.45 69,107 66,107 | R3.2 60.9,107 66,107 | 66,107 N5.3
N$9  (2 unrouted)
N$10  (1 unrouted)
N$11  (1 unrouted)
N$13  (2 unrouted)
N$14  (1 unrouted)
N$15  (3 unrouted)
N$16  (1 unrouted)
N$17  (1 unrouted)
  Top 1: N5.1 67.35,111.4 68.7,111.4 68.9,111.2 R13.1
N$18  (1 unrouted)
N$19  (2 unrouted)
N$20  (1 unrouted)
N$21  (1 unrouted)
N$22  (2 unrouted)
N$23  (1 unrouted)
N$24  (1 unrouted)
N$25  (1 unrouted)
N$26  (3 unrouted)
N$27  (3 unrouted)
N$28  (2 unrouted)
N$29  (1 unrouted)
N$30  (3 unrouted)
N$31  (1 unrouted)
N$32  (3 unrouted)
N$33  (1 unrouted)
N$34  (2 unrouted)
N$35  (1 unrouted)
N$36  (1 unrouted)
N$37  (1 unrouted)
N$38  (2 unrouted)
N$39  (2 unrouted)
OUT+  (1 unrouted)
PUMP+  (10 unrouted)
  Route3 2: PLUS2.1 36,69 42,75 69.92,75 | 26,21 29,24 34,24 37,27 37,41 PLUS1.1 | PLUS1.1 35,43 35,42 | 35,42 35,41 | PLUS1.1 35,42
  pour Top (isolate 2): 26,66 38,70 38,29 26,29
  pour Bottom (isolate 2): 26,66 38,70 38,29 26,29
RED/AC2  (7 unrouted)
  Top 0.5: 66.1,101 JP5.1 67,101
  Route5 2: RED1.1 62,84 63,83 RED.1 68,83 70,81 92,81 110,63
  pour Top (isolate 2, no thermals): 65,105 70,105 70,100 65,100
REF  (3 unrouted)
SNUB2
  pour Top (isolate 2, rank 2): 3,104 15,104 15,97 3,97
SOURCE
  pour Top (isolate 2): 3,120 6,120 6,106 3,106
V12  (2 unrouted)
  pour Bottom (isolate 1.5): 47,72 85,72 85,35 47,35
V+  (2 unrouted)
V-  (5 unrouted)
VCC  (7 unrouted)
  Top 1: R8.2 43.9,103
VDD  (2 unrouted)
X  (3 unrouted)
